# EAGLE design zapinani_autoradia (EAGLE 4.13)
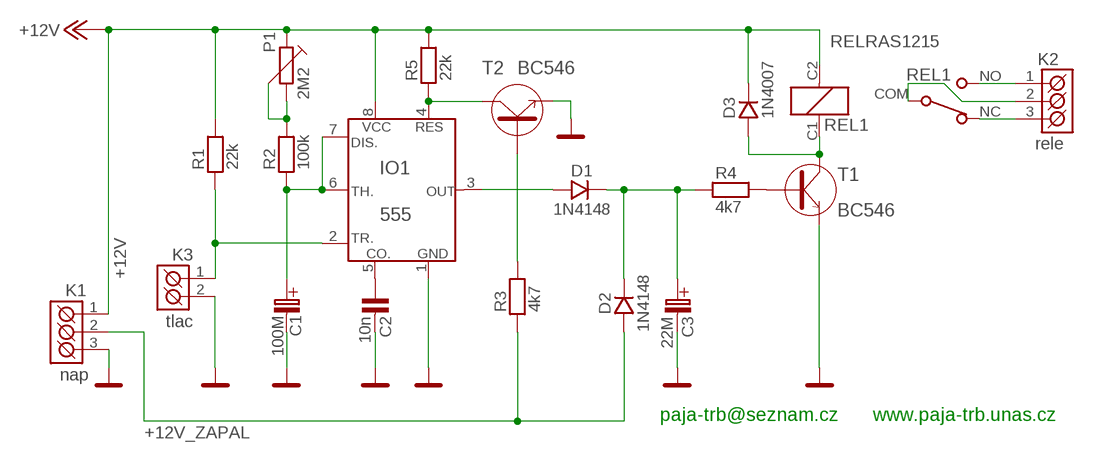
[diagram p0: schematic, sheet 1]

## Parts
C1  100M  100M/25V  [C_EL_2,5]
C2  10n  C-KERAMIK_5  [C-5]
C3  22M  C-ELEKTROLYT_2  [C-EL_2]
D1  1N4148  1N4148_7,5  [D-7,5]
D2  1N4148  1N4148_7,5  [D-7,5]
D3  1N4007  1N4007_SMD_SM-1  [SM-1]
IO1  555  [DIL8]
K1  nap  ARK500/3  [ARK500/3]
K2  rele  ARK500/3  [ARK500/3]
K3  tlac  ARK500/2  [ARK500/2]
P1  2M2  PT-10_V-LEZ  [PT10V]
R1  22k  R_7,5  [R-7,5]
R2  100k  R_7,5  [R-7,5]
R3  4k7  R_7,5  [R-7,5]
R4  4k7  R_7,5  [R-7,5]
R5  22k  R_SMD_1206  [1206]
REL1  RELRAS1215  RELRAS15  [RELE_RAS]
T1  BC546  [TO-92]
T2  BC546  [TO-92]

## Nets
+12V: D3.K IO1.8(VCC) K1.1(K1) P1.1 R1.2 R5.2 REL1.C2(RE:C2)
+12V_ZAPAL: D2.A K1.2(K2) R3.1
GND: C1.C-(C_EL-) C2.2 C3.C-(C_EL-) IO1.1(GND) K1.3(K3) K3.2(K2) T1.3(E) T2.3(E)
N$1: D1.A IO1.3(OUT)
N$2: C3.C+(C_EL+) D1.K D2.K R4.1
N$3: R4.2 T1.2(B)
N$4: D3.A REL1.C1(RE:C1) T1.1(C)
N$5: P1.2 P1.3 R2.2
N$6: C2.1 IO1.5(CO.)
N$7: C1.C+(C_EL+) IO1.6(TH.) IO1.7(DIS.) R2.1
N$8: IO1.2(TR.) K3.1(K1) R1.1
N$10: IO1.4(RES) R5.1 T2.1(C)
N$11: R3.2 T2.2(B)
N$12: K2.1(K1) REL1.NO(SW:NO)
N$13: K2.3(K3) REL1.NC(SW:NC)
N$14: K2.2(K2) REL1.COM(SW:COM)

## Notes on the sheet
- paja-trb@seznam.cz | www.paja-trb.unas.cz

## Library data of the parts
C1 = #PaJa_C-el:100M/25V
C2 = #PaJa_17:C-KERAMIK: Kondenzator - keramicky
C3 = #PaJa_18:C-ELEKTROLYT: Kondenzator - elektrolyticky
D1 D2 = #PaJa_17:1N4148: Univerzalni dioda - 0,15A, 75V
D3 = #PaJa_18:1N4007: Usmernovaci dioda - 1A, 1000V
IO1 = #PaJa_17:555: IO - Casovac 555
K1 K2 = #PaJa_17:ARK500/3: Svorkovnice - roztec 5mm - trojita
K3 = #PaJa_18:ARK500/2: Svorkovnice - roztec 5mm - dvojita
P1 = #PaJa_17:PT-10: Trimr - 10,3mm
R1 R2 R4 R5 = #PaJa_17:R: Rezistor
R3 = #PaJa_18:R: Rezistor
REL1 = #PaJa_18:RELRAS??15: RELE - 1x prepinaci, 5V, 12V, 24V max. spinany proud = 15A
T1 T2 = #PaJa_18:BC546: Tranzistor NPN - Univerzalni NF - Ic=0,1A

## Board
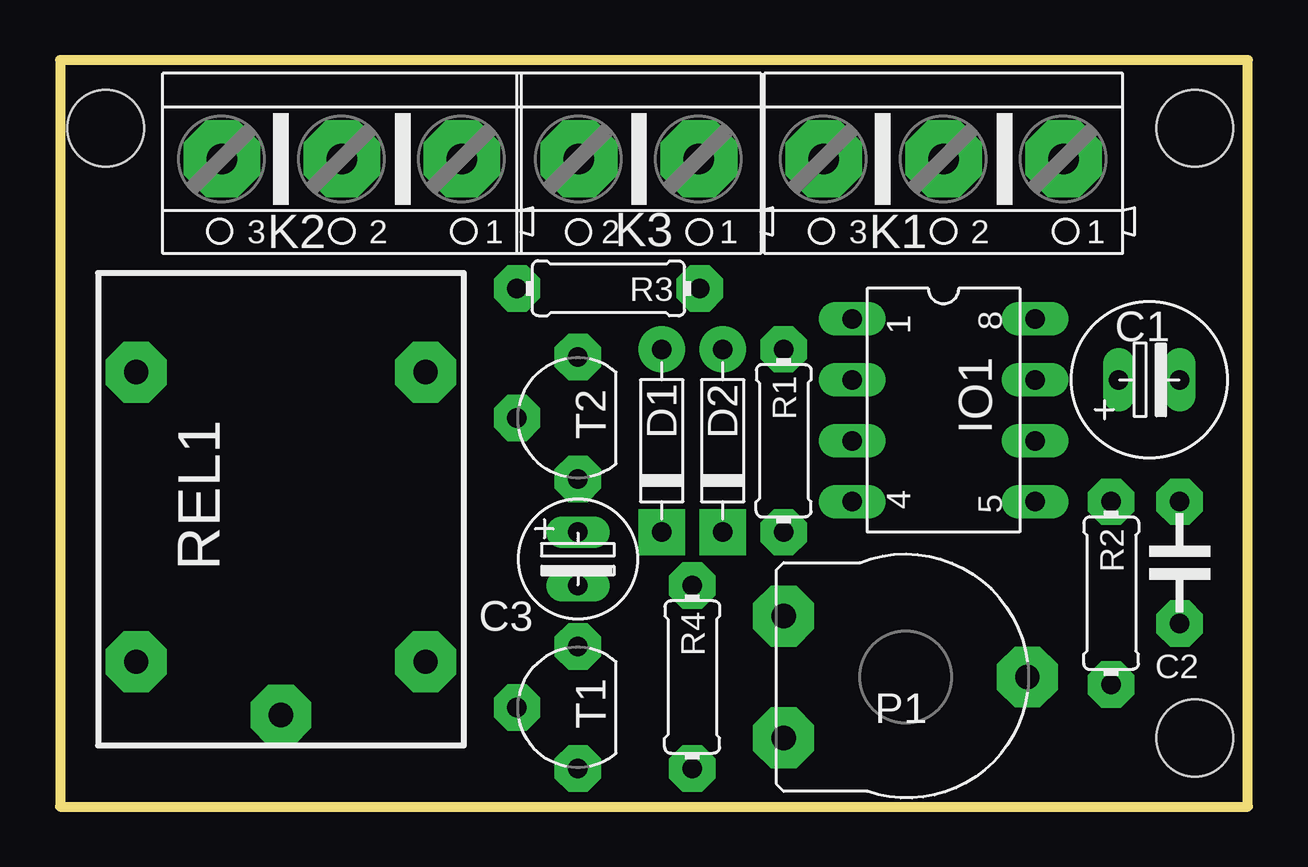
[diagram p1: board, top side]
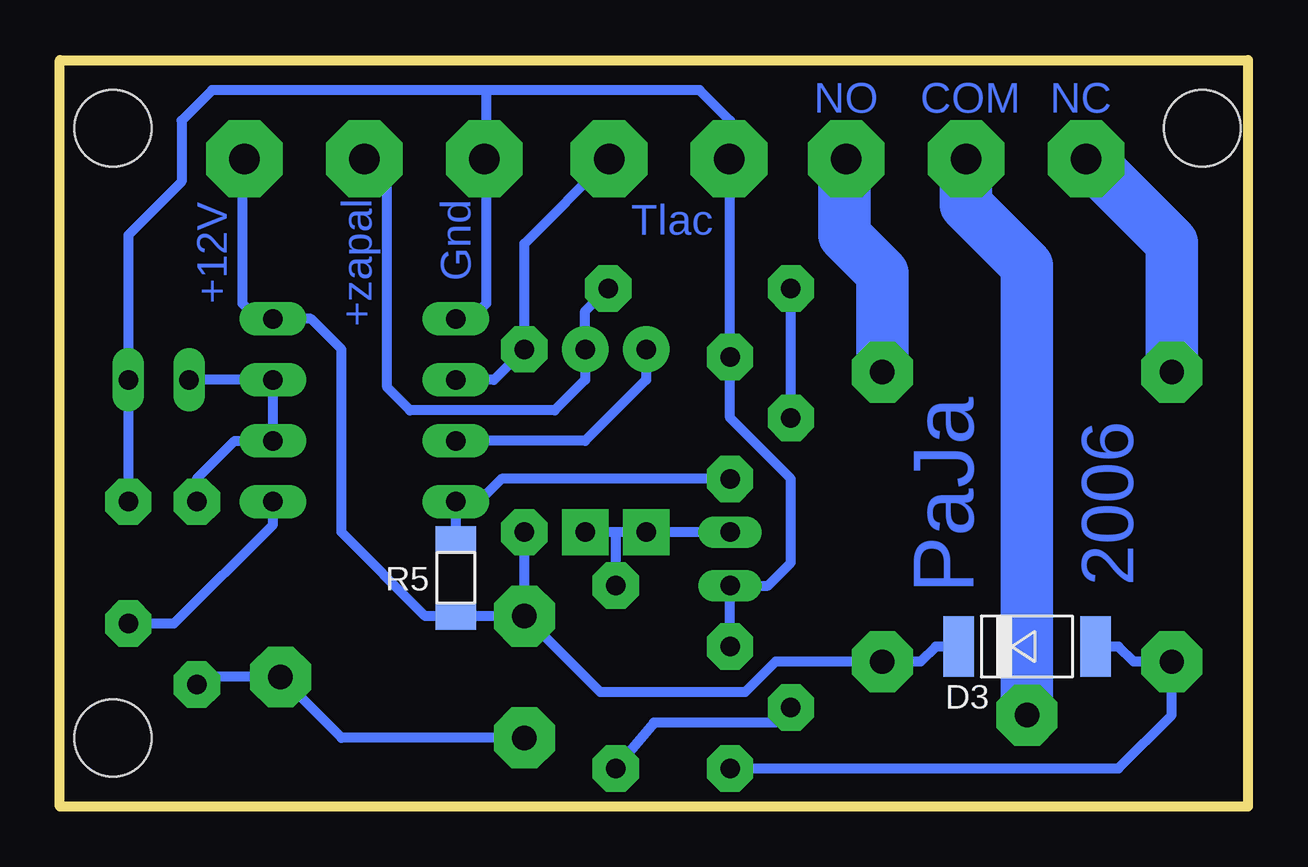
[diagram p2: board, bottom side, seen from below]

Size 49.52 x 31.11 mm. Coordinates in mm from the lower left corner, seen from the top.
Outline: 0,0 49.52,0 49.52,31.11 0,31.11 0,0
Copper layers (1*16): Top 0.035mm / dielectric 1.5mm / Bottom 0.035mm
Design rules "default": minimum track width 10mil, minimum drill 24mil, track to track 8mil, track to pad 8mil, pad to pad 8mil, via to via 8mil, smd to smd 8mil, copper to edge 40mil, drill to drill 8mil, minimum pad ring 10mil, minimum via ring 8mil, stop-mask expansion 4mil, vias tented up to drill 0mil, thermal gap 10mil
Holes 3.2 mm at 47.31,2.86 1.91,28.26 47.31,28.26

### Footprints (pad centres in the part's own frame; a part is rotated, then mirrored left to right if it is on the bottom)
C_EL_2,5 = drill 0.813 pad 1.27 long: C+ -1.27,0; C- 1.27,0
C-5 = drill 0.813 pad 1.93 octagon: 1 -2.54,0; 2 2.54,0
C-EL_2 = drill 0.813 pad 1.27 long: C+ 0,0; C- 2.223,0
D-7,5 = drill 0.813 pad 1.93 round: A -3.81,0 | drill 0.813 pad 1.93 square: K 3.81,0
SM-1 = smd 1.27 x 2.54: A 2.54,0; K -3.175,0
DIL8 = drill 0.813 pad 1.4 long: 1 -3.81,-3.81; 2 -1.27,-3.81; 3 1.27,-3.81; 4 3.81,-3.81; 5 3.81,3.81; 6 1.27,3.81; 7 -1.27,3.81; 8 -3.81,3.81
ARK500/3 = drill 1.27 pad 3.2 octagon: 1 -5,0; 2 0,0; 3 5,0
ARK500/2 = drill 1.27 pad 3.2 octagon: 1 -2.5,0; 2 2.5,0
PT10V = drill 1.016 pad 2.54 octagon: 1 -2.54,-5.08; 2 2.54,-5.08; 3 0,5.08
R-7,5 = drill 0.813 pad 1.93 octagon: 1 -3.81,0; 2 3.81,0
1206 = smd 1.143 x 1.702: 1 -1.587,0; 2 1.587,0
RELE_RAS = drill 1.016 pad 2.54 octagon: C1 -6.35,6.032; C2 -6.35,-6.032; COM -8.572,0; NC 5.715,6.032; NO 5.715,-6.032
TO-92 = drill 0.813 pad 1.93 octagon: 1 0,2.54; 2 2.54,0; 3 0,-2.54

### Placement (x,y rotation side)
C1  45.4,17.78 0 top
C2  46.67,10.16 90 top
C3  21.59,11.43 270 top
D1  25.08,15.24 270 top
D2  27.62,15.24 270 top
D3  8.89,6.67 0 bottom
IO1  36.83,16.51 270 top
K1  36.83,26.99 180 top
K2  11.75,26.99 180 top
K3  24.13,26.99 180 top
P1  35.24,5.4 270 top
R1  30.16,15.24 270 top
R2  43.81,8.89 270 top
R3  22.86,21.59 180 top
R4  26.35,5.4 270 top
R5  33.02,9.53 270 bottom
REL1  9.21,12.38 90 top
T1  21.59,4.13 180 top
T2  21.59,16.19 180 top

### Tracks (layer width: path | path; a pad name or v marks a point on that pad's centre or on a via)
+12V
  Bottom 0.406: P1.1 R1.2 | P1.1 26.99,4.76 20.96,4.76 19.69,6.03 REL1.C2 13.65,6.03 13.02,6.67 D3.K | K1.1 41.91,26.99 41.91,20.95 41.28,20.32 IO1.8 39.05,20.32 37.78,19.05 37.78,11.43 34.29,7.94 R5.2 P1.1
+12V_ZAPAL
  Bottom 0.406: K1.2 35.88,26.04 35.88,17.46 34.92,16.51 28.89,16.51 27.62,17.78 D2.A 27.62,20.64 R3.1
GND
  Bottom 0.406: C2.2 C1.C- 46.67,23.81 44.45,26.04 44.45,28.57 43.18,29.84 31.75,29.84 | IO1.1 32.39,20.32 31.75,20.95 31.75,26.91 K1.3 31.75,26.99 31.75,29.84 | T1.3 C3.C- 20,9.21 19.05,10.16 19.05,13.65 21.59,16.19 T2.3 21.59,26.99 | 31.75,29.84 22.86,29.84 21.59,28.57 21.59,26.99 | 21.59,26.99 K3.2
N$1
  Bottom 0.406: IO1.3 27.62,15.24 25.08,17.78 D1.A
N$2
  Bottom 0.406: 26.35,11.43 D1.K C3.C+ | 26.35,11.43 D2.K | 26.35,11.43 R4.1
N$3
  Bottom 0.406: T1.2 19.69,3.49 24.77,3.49 R4.2
N$4
  Bottom 0.406: T1.1 5.4,1.59 3.18,3.81 REL1.C1 4.76,6.03 5.4,6.67 D3.A
N$5
  Bottom 0.406: R2.2 43.5,5.4 P1.3 37.78,2.86 P1.2
N$6
  Bottom 0.406: C2.1 44.77,7.62 40.64,11.75 IO1.5
N$7
  Bottom 0.406: C1.C+ IO1.7 IO1.6 42.23,15.24 43.81,13.65 R2.1
N$8
  Bottom 0.406: IO1.2 31.43,17.78 R1.1 30.16,23.45 K3.1
N$10
  Bottom 0.406: T2.1 31.12,13.65 32.07,12.7 IO1.4 R5.1
N$11
  Bottom 0.406: T2.2 R3.2
N$12
  Bottom 2.184: REL1.NO 15.24,22.23 16.83,23.81 16.83,26.99 K2.1
N$13
  Bottom 2.184: K2.3 6.67,26.99 3.18,23.5 REL1.NC
N$14
  Bottom 2.184: REL1.COM 9.21,22.54 11.75,25.08 K2.2

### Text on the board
Bottom: NC | COM | NO | Tlac | Gnd | +12V | +zapal | 2006 | PaJa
